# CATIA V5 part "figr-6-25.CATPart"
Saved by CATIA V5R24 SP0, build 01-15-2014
Part number: Part1
Bounding box of the stored display mesh (mm): x -70 to 0, y 0 to 90, z -45 to 145
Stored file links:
  D:\KAVITA\CATIA V5-6R2014 Project_ Kavita\CATIA V5-6R2014_partfiles\Partfiles\c06_catia_v5-6r2014_prt\figr-6-25.CATPart
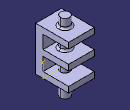
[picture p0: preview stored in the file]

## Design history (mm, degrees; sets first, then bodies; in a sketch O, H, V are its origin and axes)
Body1 (main body)
  Sketch1 on zx-plane, origin (0, 0, 0), H (-1, 0, 0), V (0, 0, 1)
    line L1 (0, 0) -> (70, 0)
    line L2 (70, 0) -> (70, 120)
    line L3 (70, 120) -> (0, 120)
    line L4 (0, 120) -> (0, 0)
    length L3 = 70
    length L2 = 120
    horizontal: L1 H, L3 H
    vertical: L2 V, L4 V
  Pad1: profile Sketch1, direction (0, 1, 0), length 20
  Sketch2 on end face of Pad1, origin (0, 20, 0), H (-1, 0, 0), V (0, 0, 1)
    projected line E1 (70, 120) -> (0, 120) from edge [face of Pad1 from Sketch1.L3 | end face of Pad1]
    point P1 (70, 120)
    line L1 (70, 120) -> (70, 104)
    line L2 (70, 104) -> (0, 104)
    line L3 (0, 104) -> (0, 120)
    point P3 (70, 120)
    length L1 = 16
    horizontal: L2 H
    vertical: L1 V, L3 V
    coincidence: P1 P3
  Sketch3 on end face of Pad1, origin (0, 20, 0), H (-1, 0, 0), V (0, 0, 1)
  Pad2: profile Sketch2, direction (0, 1, 0), length 70
  Sketch4 on end face of Pad1, origin (0, 20, 0), H (-1, 0, 0), V (0, 0, 1)
    projected line E1 (0, 0) -> (70, 0) from edge [face of Pad1 from Sketch1.L1 | end face of Pad1]
    point P1 (0, 0)
    point P3 (0, 16)
    line L1 (0, 16) -> (70, 16)
    line L2 (70, 16) -> (70, 0)
    line L3 (0, 0) -> (0, 16)
    point P5 (0, 0)
    length L2 = 16
    coincidence: P3 V, P1 P5
    horizontal: L1 H
    vertical: L2 V, L3 V
  Pad3: profile Sketch4, direction (0, 1, 0), length 70
  Sketch5 on end face of Pad1, origin (0, 20, 0), H (-1, 0, 0), V (0, 0, 1)
    point P1 (0, 68)
    line L1 (0, 68) -> (70, 68)
    line L2 (70, 68) -> (70, 52)
    line L3 (70, 52) -> (0, 52)
    line L4 (0, 52) -> (0, 68)
    coincidence: P1 V
    horizontal: L1 H, L3 H
    vertical: L2 V, L4 V
  Pad4: profile Sketch5, direction (0, 1, 0), length 70
  Sketch6 on face of Pad2, origin (0, 0, 120), H (1, 0, 0), V (0, 1, 0)
    circle A1 centre (-35, 45) radius 12.5
    radius A1 = 12.5
  Pad5: profile Sketch6, direction (0, 0, 1), length 25, opposite side length 165
  Fillet1: radius 5, on 1 edge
